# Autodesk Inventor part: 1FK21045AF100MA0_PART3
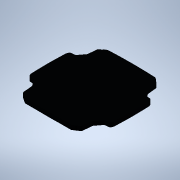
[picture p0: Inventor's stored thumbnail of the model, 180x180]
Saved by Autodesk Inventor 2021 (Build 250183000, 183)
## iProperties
Created: 2025-04
Part Number: 1FK21045AF100MA0_PART3
Material: Generic
Catalog Web Link: www.3dfindit.com
Description: -Servo synchronous motor
Document SubType Name: Modeling
Designer: psAdmin
Mass: 21.7019 g
Surface Area: 120.085 cm^2
Volume: 21.7019 cm^3
Density: 1 g/cm^3
Appearance: PSOLRGB-38-46-56
Category: PARTsolutions
Title: 1FK21045AF100MA0_PART3
Author: Cadenas PARTsolutions
Comments: Servo synchronous motor
Sending System: PARTsolutions
Preprocessor: ST-DEVELOPER v19.3
PSOL_IDENT_0: {$CADENAS_DATA/23d-libs/siemens_ag/_cat_/52/6b/1fk21045af100ma0.prj},213 {VTYP=3D},{NB=1FK21045AF100
PSOL_IDENT_1: MA0_PART3},{LINA=1FK21045AF100MA0_PART3},{NN=1FK21045AF100MA0_PART3},{NOPRJ=TRUE},{DATE=19.08.2025 1
PSOL_IDENT_2: 4:00:38},{GEOMDATE=30.07.2025 02:01:45},{VERSION=},{LINEID=10},{WBVAR=},{WBNUMERIC=}  {NB=1FK21045AF
PSOL_IDENT_3: 100MA0_PART3},{LINA=1FK21045AF100MA0_PART3},{KT=DUMMY},{PREVIEW=../../../_pool_/cb/72/p_d211_xx_0043
PSOL_IDENT_4: 4j.png},{DESCSHORT=SIMOTICS S-1FK2 HD, SINAMICS S210 3AC 400V-480V, 2.4 Nm, 3000 rpm},{DESCLONG=SIMO
PSOL_IDENT_5: TICS S-1FK2 HD servo motor M0=2.4 Nm; PN = 0.75 kW at nN=3000 rpm (380-480 V); PN = 0.375 kW at nN=1
PSOL_IDENT_6: 500 rpm (200-240 V); with holding brake; degree of protection IP64; cylindrical shaft D19x40mm; abso
PSOL_IDENT_7: lute encoder 22-bit + 12-bit multiturn (encoder AM22DQC); with OCC interface; plug size M17, rotatab
PSOL_IDENT_8: le; SIMOTICS S-1FK2 servomotorfor a wide range of uses in industrial environments. SIMOTICS S‑1FK2 s
PSOL_IDENT_9: ervomotors are compact synchronous motors with a high dynamic performance that set themselves apart
PSOL_IDENT_10: as a result of their high power density, degree of protection and overload capability. The motors ar
PSOL_IDENT_11: e available in two variants: as High Dynamic variant (highest dynamic performance as a result of the
PSOL_IDENT_12: low intrinsic moment of inertia for applications demanding a high dynamic performance with low move
PSOL_IDENT_13: d masses) - and as Compact variant (precise and stable closed-loop control for medium up to large mo
PSOL_IDENT_14: ved masses as a result of a medium intrinsic moment of inertia). SIMOTICSS‑1FK2 servomotors fully ex
PSOL_IDENT_15: ploit their strengths in a system with the SINAMICSS210 frequency converter and simple connection us
PSOL_IDENT_16: ing the one cable connection (OCC). Advantages include the short control and positioning times, fast
PSOL_IDENT_17: and precise correction of disturbing quantities as well as stable control with a high dynamic perfo
PSOL_IDENT_18: rmance. The servo motors can be configured to address a wide range of requirements. For example with
PSOL_IDENT_19: and without holding brake, IP64 or IP65 degree of protection, singleturn or multiturn absolute enco
PSOL_IDENT_20: ders - to name just a few. Further, the servomotors are available in different shaft heights extendi
PSOL_IDENT_21: ng from 20 to 100. A shaft sealing ring is available to achieve an IP65 degree of protection and for
PSOL_IDENT_22: subsequent mounting at the motor or as spare part. SIMOTICS - the optimum motor for each and every
PSOL_IDENT_23: motion control application.},{INTNO=804766906411},{SUPPLIERALTNO=1FK2104-5AF10-0MA0},{MANUID=1FK2104
PSOL_IDENT_24: 5AF100MA0},{MANUNAME=Siemens},{MANUTYPEDESC=Synchronous motor 1FK2-HD 2.4 NM},{AAU732=SIMOTICS},{AAO
PSOL_IDENT_25: 057=S-1FK2},{AAU734=SIMOTICS S-1FK2 HD servo motor M0=2.4 Nm; PN = 0.75 kW at nN=3000 rpm (380-480 V
PSOL_IDENT_26: ); PN = 0.375 kW at nN=1500 rpm (200-240 V); with holding brake; degree of protection IP64; cylindri
PSOL_IDENT_27: cal shaft D19x40mm; absolute encoder 22-bit + 12-bit multiturn (encoder AM22DQC); with OCC interface
PSOL_IDENT_28: ; plug size M17, rotatable;},{AAW338=Synchronous motor 1FK2-HD 2.4 NM},{AAO742=SIMOTICS},{AAO663=404
PSOL_IDENT_29: 2948693070},{NOCUPEROU=1},{PRICEQUANTITY=1},{QUANTITYMIN=1},{QUANTITYINT=1},{CTN=85015100},{COO=DE},
PSOL_IDENT_30: {AAO676=1FK2104-5AF10-0MA0},{AAO677=Siemens AG},{ORDERUNIT=C62},{CONTENTUNIT=C62}
NB: 1FK21045AF100MA0_PART3
NT: Servo synchronous motor
NBSYN: $MANUID._PART3
LINA: 1FK21045AF100MA0_PART3
CATALOG: SIEMENS
PREVIEW: ../../../_pool_/cb/72/p_d211_xx_00434j.png
DESCSHORT: SIMOTICS S-1FK2 HD, SINAMICS S210 3AC 400V-480V, 2.4 Nm, 3000 rpm
DESCLONG: SIMOTICS S-1FK2 HD servo motor M0=2.4 Nm; PN = 0.75 kW at nN=3000 rpm (380-480 V); PN = 0.375 kW at nN=1500 rpm (200-240 V); with holding brake; degree of prote
INTNO: 804766906411
SUPPLIERALTNO: 1FK2104-5AF10-0MA0
MANUID: 1FK21045AF100MA0
MANUNAME: Siemens
MANUTYPEDESC: Synchronous motor 1FK2-HD 2.4 NM
AAU732: SIMOTICS
AAO057: S-1FK2
AAU734: SIMOTICS S-1FK2 HD servo motor M0=2.4 Nm; PN = 0.75 kW at nN=3000 rpm (380-480 V); PN = 0.375 kW at nN=1500 rpm (200-240 V); with holding brake; degree of prote
AAW338: Synchronous motor 1FK2-HD 2.4 NM
AAO742: SIMOTICS
AAO663: 4042948693070.0
NOCUPEROU: 1
PRICEQUANTITY: 1
QUANTITYMIN: 1
QUANTITYINT: 1
CTN: 85015100
COO: DE
ARTICLENO: 1FK21045AF100MA0_PART3
BOMINFO: 1FK21045AF100MA0_PART3
CREATOR: CADENAS GmbH
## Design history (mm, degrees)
feature "2025_04_17_15_34_52_0223"
body "Solid1"
